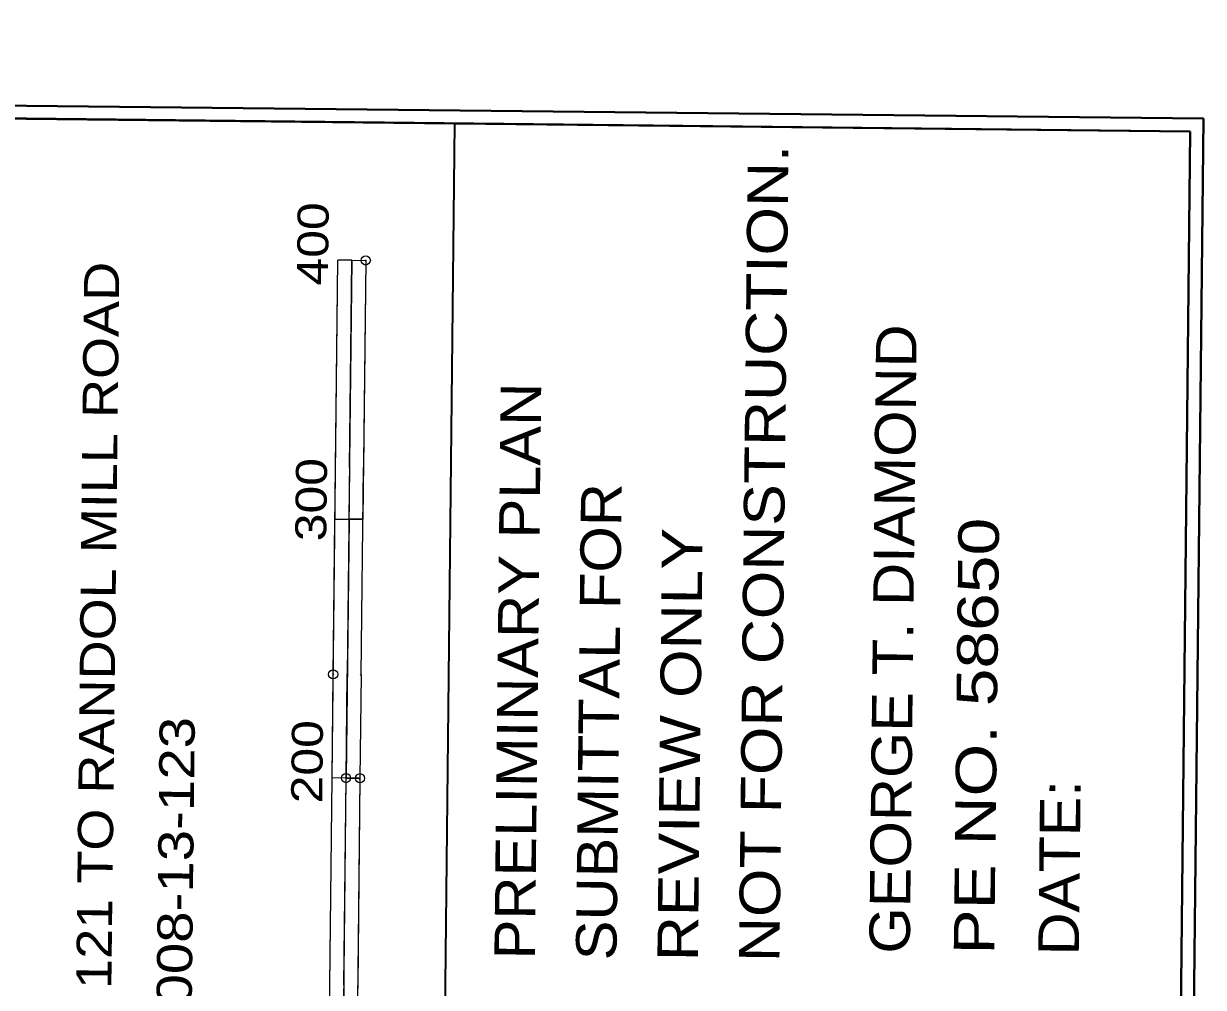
# Model space of a CAD drawing. Extents: x 2356576 to 2377878, y 6966390 to 6990634.
# Drawn here: x 2366707.9 to 2367163.6, y 6990262.2 to 6990634.4 of the extents above; entities that cross this region are included whole.
import ezdxf

# ---------------------------------------------------------------- set-up
doc = ezdxf.new("R2010")
doc.units = 0
doc.header["$LTSCALE"] = 7.1
doc.header["$PDMODE"] = 32
doc.header["$PDSIZE"] = 3.55
doc.layers.add('19', color=7, linetype='Continuous', lineweight=13)
doc.layers.add('8', color=7, linetype='Continuous', lineweight=13)

msp = doc.modelspace()

# ---------------------------------------------------------------- linework, layer by layer
at = {"layer": '19', "lineweight": 35}
for p, q in [((2367158.576, 6990592.767), (2366453.06, 6990600.603)), ((2366874.428, 6990595.923), (2366865.462, 6989788.709)), ((2367158.576, 6990592.767), (2367149.612, 6989785.553))]:
    msp.add_line(p, q, dxfattribs=at)
at = {"layer": '19'}
for p, q in [((2366824.855, 6990143.089), (2366827.075, 6990343.078)), ((2366826.187, 6990263.082), (2366827.075, 6990343.078)), ((2366832.469, 6990343.018), (2366827.075, 6990343.078)), ((2366832.468, 6990343.018), (2366827.075, 6990343.078)), ((2366832.466, 6990342.737), (2366832.75, 6990343.015)), ((2366832.467, 6990342.831), (2366832.656, 6990343.016)), ((2366837.861, 6990342.958), (2366832.468, 6990343.018)), ((2366832.468, 6990342.925), (2366832.562, 6990343.017)), ((2366832.55, 6990343.017), (2366832.469, 6990343.1)), ((2366832.645, 6990343.016), (2366832.47, 6990343.194)), ((2366837.863, 6990342.958), (2366836.974, 6990262.962)), ((2366837.859, 6990342.65), (2366837.555, 6990342.962)), ((2366837.609, 6990342.961), (2366837.864, 6990343.21)), ((2366837.86, 6990342.745), (2366837.649, 6990342.96)), ((2366837.703, 6990342.96), (2366837.863, 6990343.116)), ((2366837.861, 6990342.839), (2366837.743, 6990342.959)), ((2366837.862, 6990342.933), (2366837.837, 6990342.959)), ((2366825.299, 6990183.087), (2366826.187, 6990263.082)), ((2366826.187, 6990263.038), (2366826.231, 6990263.082)), ((2366831.58, 6990263.022), (2366830.692, 6990183.027)), ((2366836.085, 6990182.967), (2366836.974, 6990262.962))]:
    msp.add_line(p, q, dxfattribs=at)
at = {"layer": '19', "lineweight": 40}
msp.add_lwpolyline([(2363758.773, 6990629.355), (2367158.576, 6990592.767), (2366922.891, 6968646.236), (2363523.088, 6968682.826)], close=True, dxfattribs=at)
at = {"layer": '19'}
msp.add_lwpolyline([(2366831.474, 6990243.042), (2366832.584, 6990343.017), (2366837.863, 6990342.958), (2366836.752, 6990242.983)], close=True, dxfattribs=at)
msp.add_lwpolyline([(2366831.58, 6990263.022), (2366832.469, 6990343.018), (2366837.863, 6990342.958)], dxfattribs=at)
for p in [(2366832.468, 6990343.018), (2366837.863, 6990342.958)]:
    msp.add_point(p, dxfattribs=at)
at = {"layer": '8', "lineweight": 35}
for p, q in [((2367158.576, 6990592.767), (2366453.06, 6990600.603)), ((2366874.428, 6990595.923), (2366865.462, 6989788.709)), ((2367158.576, 6990592.767), (2367149.612, 6989785.553))]:
    msp.add_line(p, q, dxfattribs=at)
at = {"layer": '8'}
for p, q in [((2366827.075, 6990343.078), (2366829.295, 6990543.067)), ((2366828.407, 6990463.071), (2366829.295, 6990543.067)), ((2366834.689, 6990543.007), (2366829.295, 6990543.067)), ((2366834.686, 6990542.726), (2366834.97, 6990543.004)), ((2366834.687, 6990542.82), (2366834.876, 6990543.005)), ((2366834.688, 6990542.914), (2366834.782, 6990543.006)), ((2366840.083, 6990542.947), (2366839.194, 6990462.951)), ((2366840.079, 6990542.639), (2366839.775, 6990542.951)), ((2366840.08, 6990542.734), (2366839.869, 6990542.949)), ((2366840.081, 6990542.828), (2366839.963, 6990542.948)), ((2366840.082, 6990542.922), (2366840.057, 6990542.948)), ((2366827.519, 6990383.076), (2366828.407, 6990463.071)), ((2366828.407, 6990463.027), (2366828.451, 6990463.071)), ((2366833.8, 6990463.011), (2366832.912, 6990383.016)), ((2366838.305, 6990382.956), (2366839.194, 6990462.951)), ((2366828.185, 6990443.072), (2366838.972, 6990442.952)), ((2366827.075, 6990343.078), (2366827.519, 6990383.076)), ((2366827.609, 6990383.075), (2366827.52, 6990383.166)), ((2366827.703, 6990383.074), (2366827.521, 6990383.26)), ((2366832.468, 6990343.018), (2366832.912, 6990383.016)), ((2366832.698, 6990383.018), (2366832.915, 6990383.23)), ((2366832.792, 6990383.017), (2366832.913, 6990383.135)), ((2366832.887, 6990383.016), (2366832.912, 6990383.041)), ((2366832.911, 6990382.94), (2366832.987, 6990383.015)), ((2366832.911, 6990382.846), (2366833.081, 6990383.014)), ((2366838.302, 6990382.616), (2366837.966, 6990382.96)), ((2366838.303, 6990382.711), (2366838.061, 6990382.959)), ((2366824.855, 6990143.089), (2366827.075, 6990343.078)), ((2366826.187, 6990263.082), (2366827.075, 6990343.078)), ((2366832.469, 6990343.018), (2366827.075, 6990343.078)), ((2366832.468, 6990343.018), (2366827.075, 6990343.078)), ((2366832.466, 6990342.737), (2366832.75, 6990343.015)), ((2366832.467, 6990342.831), (2366832.656, 6990343.016)), ((2366832.468, 6990342.925), (2366832.562, 6990343.017)), ((2366832.55, 6990343.017), (2366832.469, 6990343.1)), ((2366832.645, 6990343.016), (2366832.47, 6990343.194)), ((2366837.863, 6990342.958), (2366836.974, 6990262.962)), ((2366837.859, 6990342.65), (2366837.555, 6990342.962)), ((2366837.609, 6990342.961), (2366837.864, 6990343.21)), ((2366837.86, 6990342.745), (2366837.649, 6990342.96)), ((2366837.703, 6990342.96), (2366837.863, 6990343.116)), ((2366837.861, 6990342.839), (2366837.743, 6990342.959)), ((2366837.862, 6990342.933), (2366837.837, 6990342.959)), ((2366825.299, 6990183.087), (2366826.187, 6990263.082)), ((2366826.187, 6990263.038), (2366826.231, 6990263.082)), ((2366831.58, 6990263.022), (2366830.692, 6990183.027)), ((2366836.085, 6990182.967), (2366836.974, 6990262.962))]:
    msp.add_line(p, q, dxfattribs=at)
at = {"layer": '8', "lineweight": 40}
for points in [[(2363753.827, 6990634.409), (2367163.63, 6990597.713), (2366927.837, 6968641.182), (2363518.034, 6968677.88)], [(2363758.773, 6990629.355), (2367158.576, 6990592.767), (2366922.891, 6968646.236), (2363523.088, 6968682.826)]]:
    msp.add_lwpolyline(points, close=True, dxfattribs=at)
at = {"layer": '8'}
for points in [[(2366833.694, 6990443.031), (2366834.804, 6990543.006), (2366840.083, 6990542.947), (2366838.972, 6990442.972)], [(2366827.075, 6990343.078), (2366828.185, 6990443.092), (2366833.694, 6990443.031), (2366832.583, 6990343.016)], [(2366831.474, 6990243.042), (2366832.584, 6990343.017), (2366837.863, 6990342.958), (2366836.752, 6990242.983)]]:
    msp.add_lwpolyline(points, close=True, dxfattribs=at)
for points in [[(2366833.8, 6990463.011), (2366834.689, 6990543.007), (2366840.083, 6990542.947)], [(2366838.305, 6990382.956), (2366837.861, 6990342.958), (2366832.468, 6990343.018)], [(2366831.58, 6990263.022), (2366832.469, 6990343.018), (2366837.863, 6990342.958)]]:
    msp.add_lwpolyline(points, dxfattribs=at)
for p in [(2366840.083, 6990542.947), (2366827.519, 6990383.076), (2366832.468, 6990343.018), (2366837.863, 6990342.958)]:
    msp.add_point(p, dxfattribs=at)

# ---------------------------------------------------------------- texts
at = {"layer": '19'}
for s, height, width, p in [('NOT FOR CONSTRUCTION.', 15.66, 1.15, (2366999.86, 6990271.863)), ('LIMITS:  NORTH INTERCHANGE SH 121 TO RANDOL MILL ROAD', 13.58, 1.15, (2366737.852, 6989904.165)), ('GEORGE T. DIAMOND', 15.65, 1.1, (2367050.206, 6990275.145)), ('PRELIMINARY PLAN', 15.66, 1.1, (2366905.404, 6990272.911)), ('SUBMITTAL FOR', 15.66, 1.1, (2366936.892, 6990272.563)), ('PE NO. 58650', 15.65, 1.25, (2367082.844, 6990274.783)), ('REVIEW ONLY', 15.66, 1.15, (2366968.372, 6990272.213)), ('CONTROL NO.  0008-13-123', 13.58, 1.2, (2366770.906, 6990079.545)), ('200', 12, 1.2, (2366823.243, 6990333.202)), ('DATE: ', 15.65, 1.1, (2367115.484, 6990274.419))]:
    msp.add_text(s, height=height, rotation=89.364, dxfattribs=dict(at, width=width)).set_placement(p)
at = {"layer": '8'}
for s, height, width, p in [('NOT FOR CONSTRUCTION.', 15.66, 1.15, (2366999.86, 6990271.863)), ('400', 12, 1.2, (2366825.463, 6990533.191)), ('LIMITS:  NORTH INTERCHANGE SH 121 TO RANDOL MILL ROAD', 13.58, 1.15, (2366737.852, 6989904.165)), ('GEORGE T. DIAMOND', 15.65, 1.1, (2367050.206, 6990275.145)), ('PRELIMINARY PLAN', 15.66, 1.1, (2366905.404, 6990272.911)), ('300', 12, 1.2, (2366824.817, 6990434.427)), ('SUBMITTAL FOR', 15.66, 1.1, (2366936.892, 6990272.563)), ('PE NO. 58650', 15.65, 1.25, (2367082.844, 6990274.783)), ('REVIEW ONLY', 15.66, 1.15, (2366968.372, 6990272.213)), ('CONTROL NO.  0008-13-123', 13.58, 1.2, (2366770.906, 6990079.545)), ('200', 12, 1.2, (2366823.243, 6990333.202)), ('DATE: ', 15.65, 1.1, (2367115.484, 6990274.419))]:
    msp.add_text(s, height=height, rotation=89.364, dxfattribs=dict(at, width=width)).set_placement(p)

doc.saveas('drawing.dxf')
